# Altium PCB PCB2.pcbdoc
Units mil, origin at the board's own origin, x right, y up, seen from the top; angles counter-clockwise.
Board outline 4577.16 x 3555.26 mil, 4 copper layers (Top Layer, Inner1, Inner2, Bottom Layer); 87 components, 77 nets, 373 pads, 159 vias.
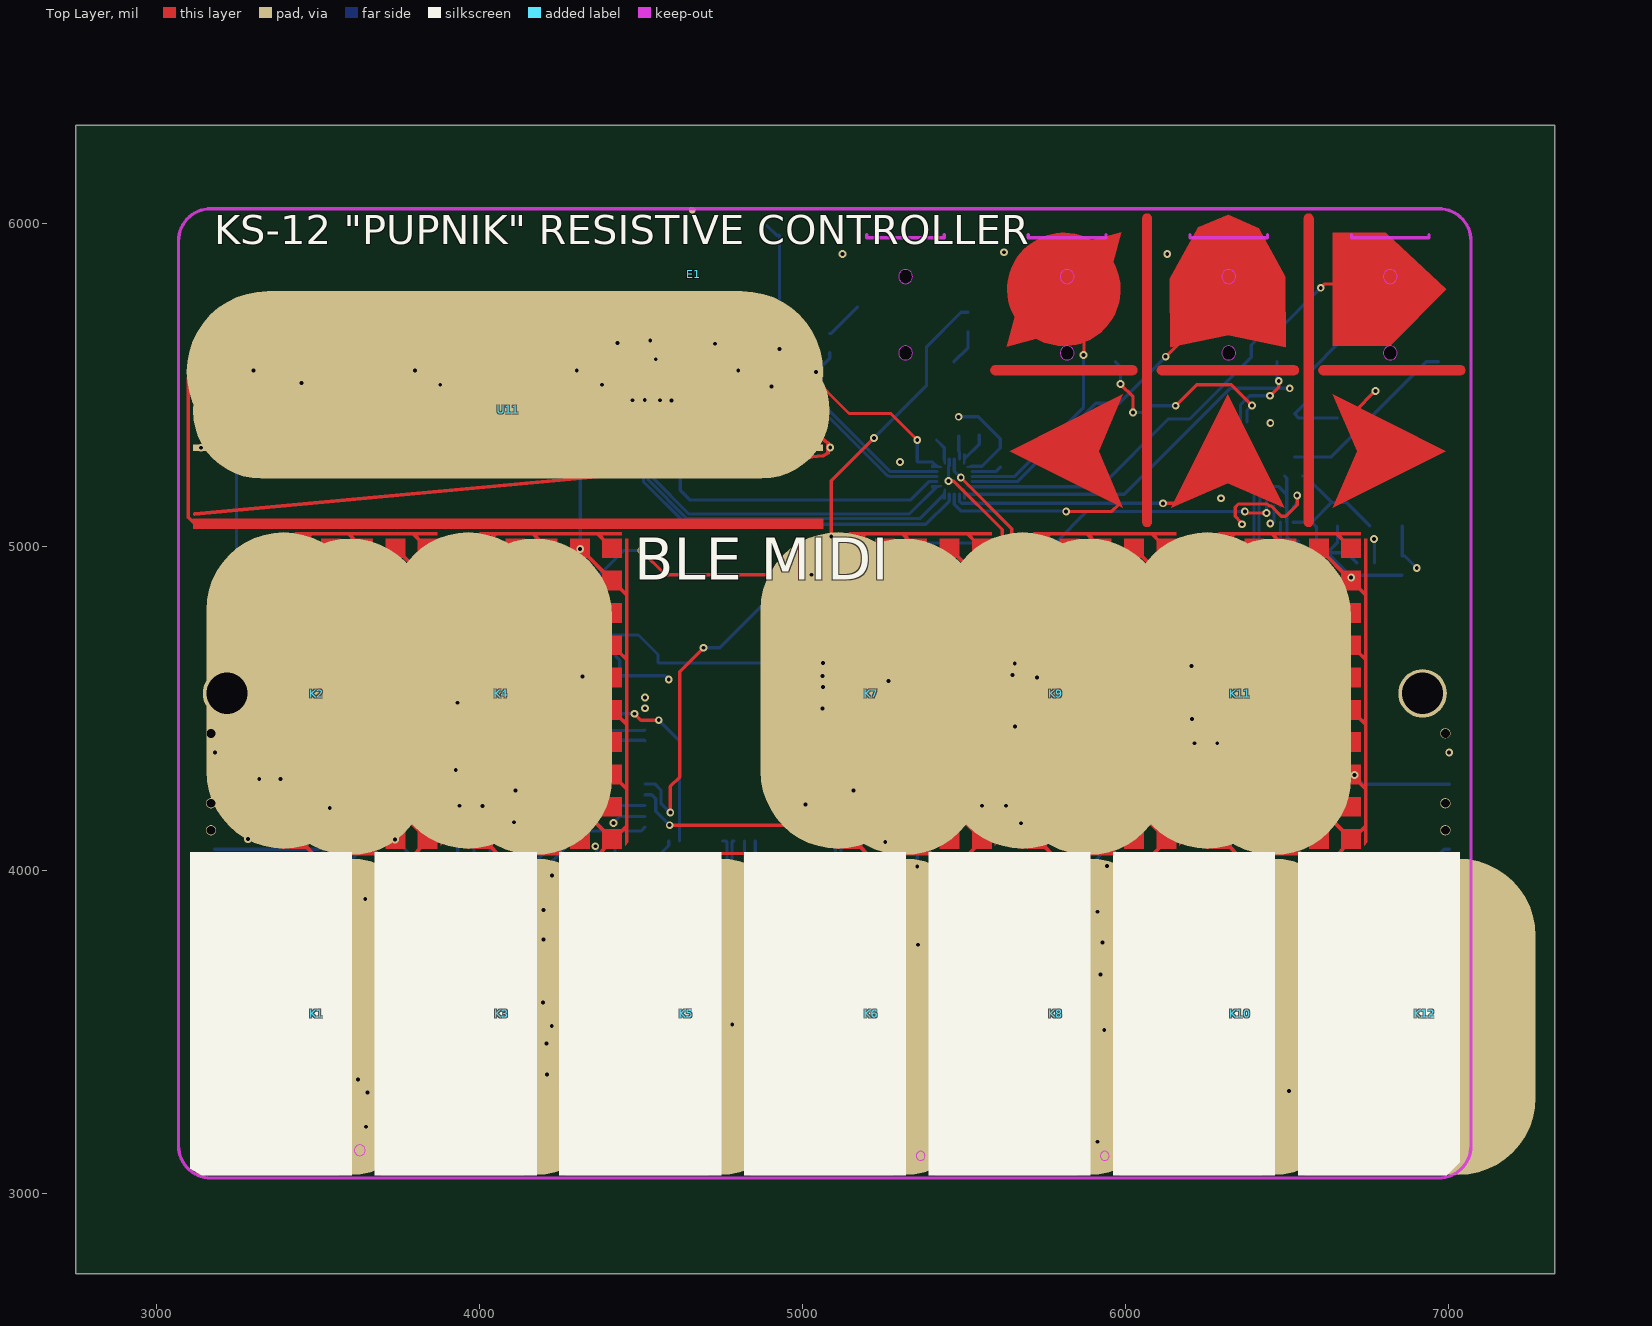
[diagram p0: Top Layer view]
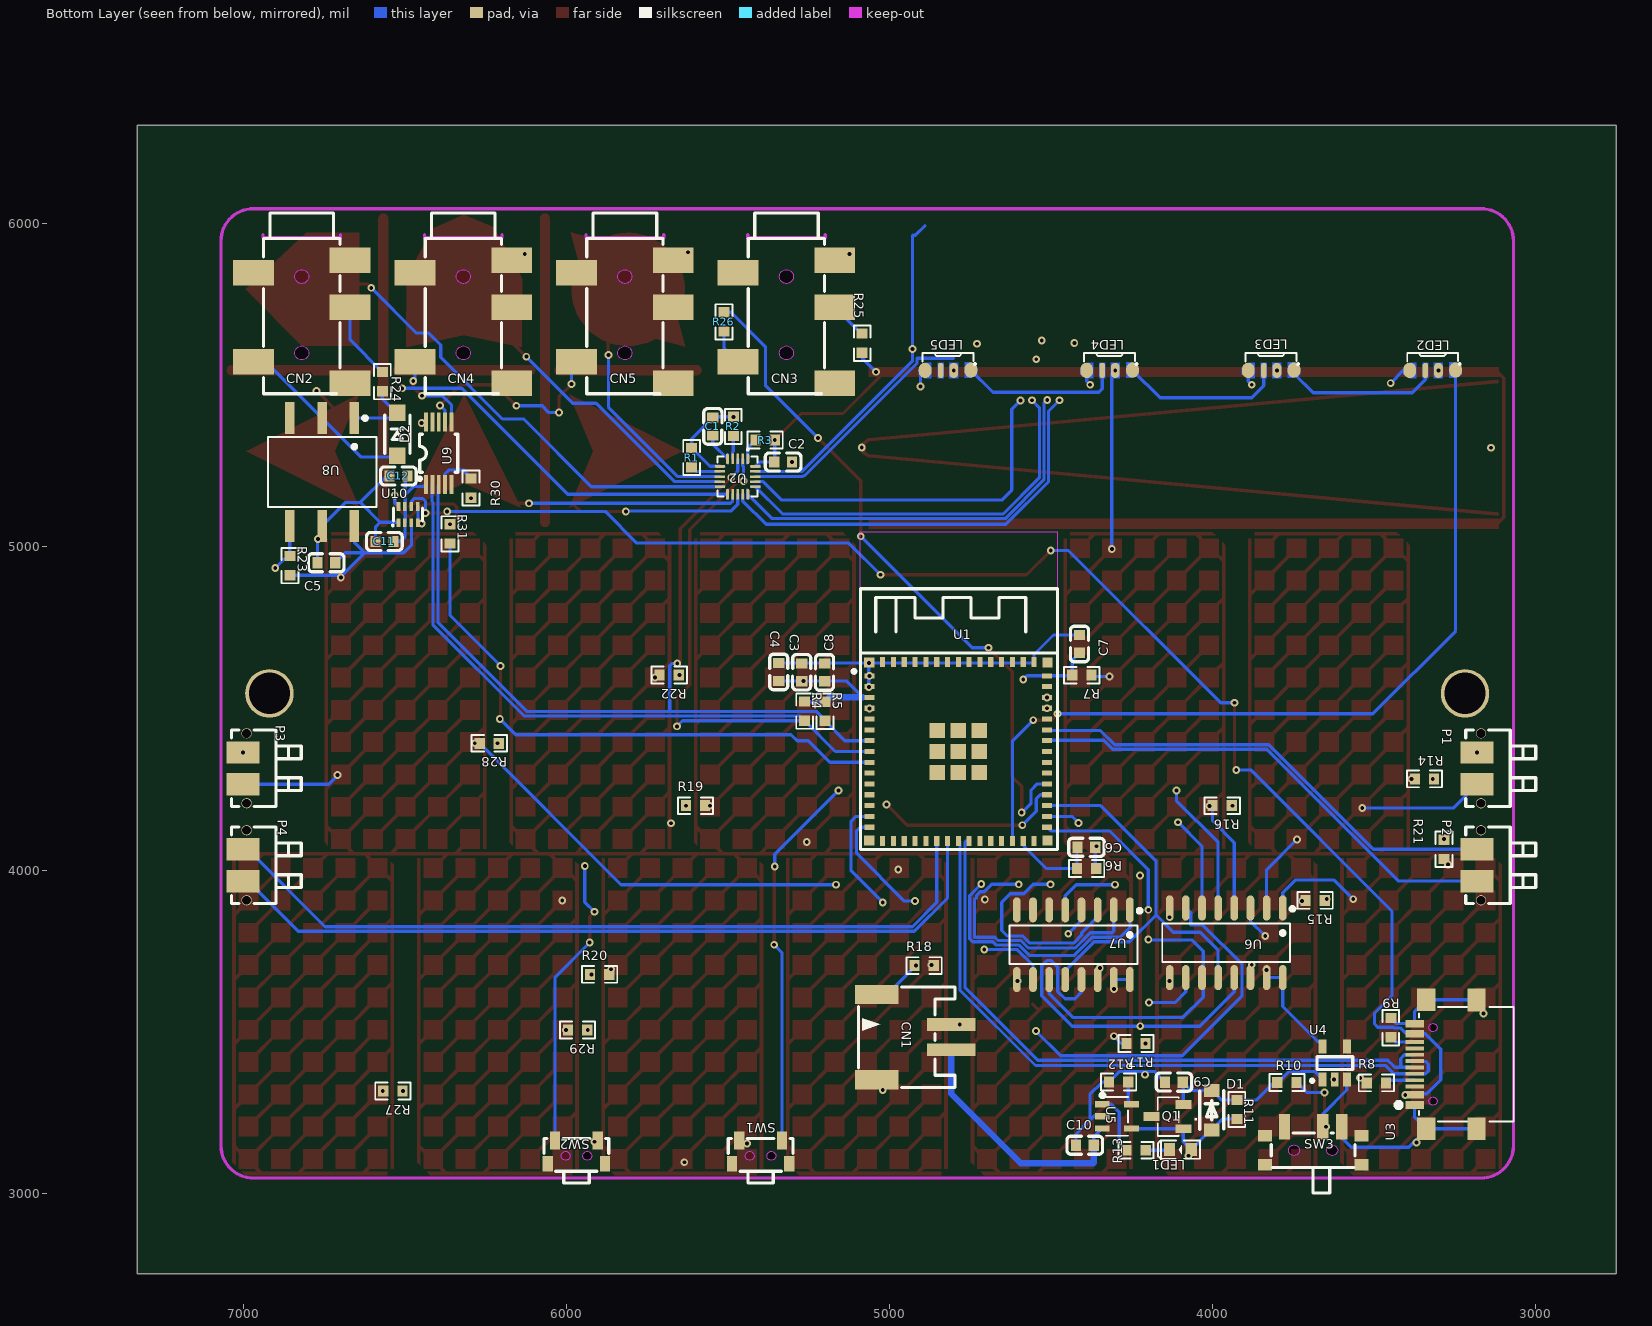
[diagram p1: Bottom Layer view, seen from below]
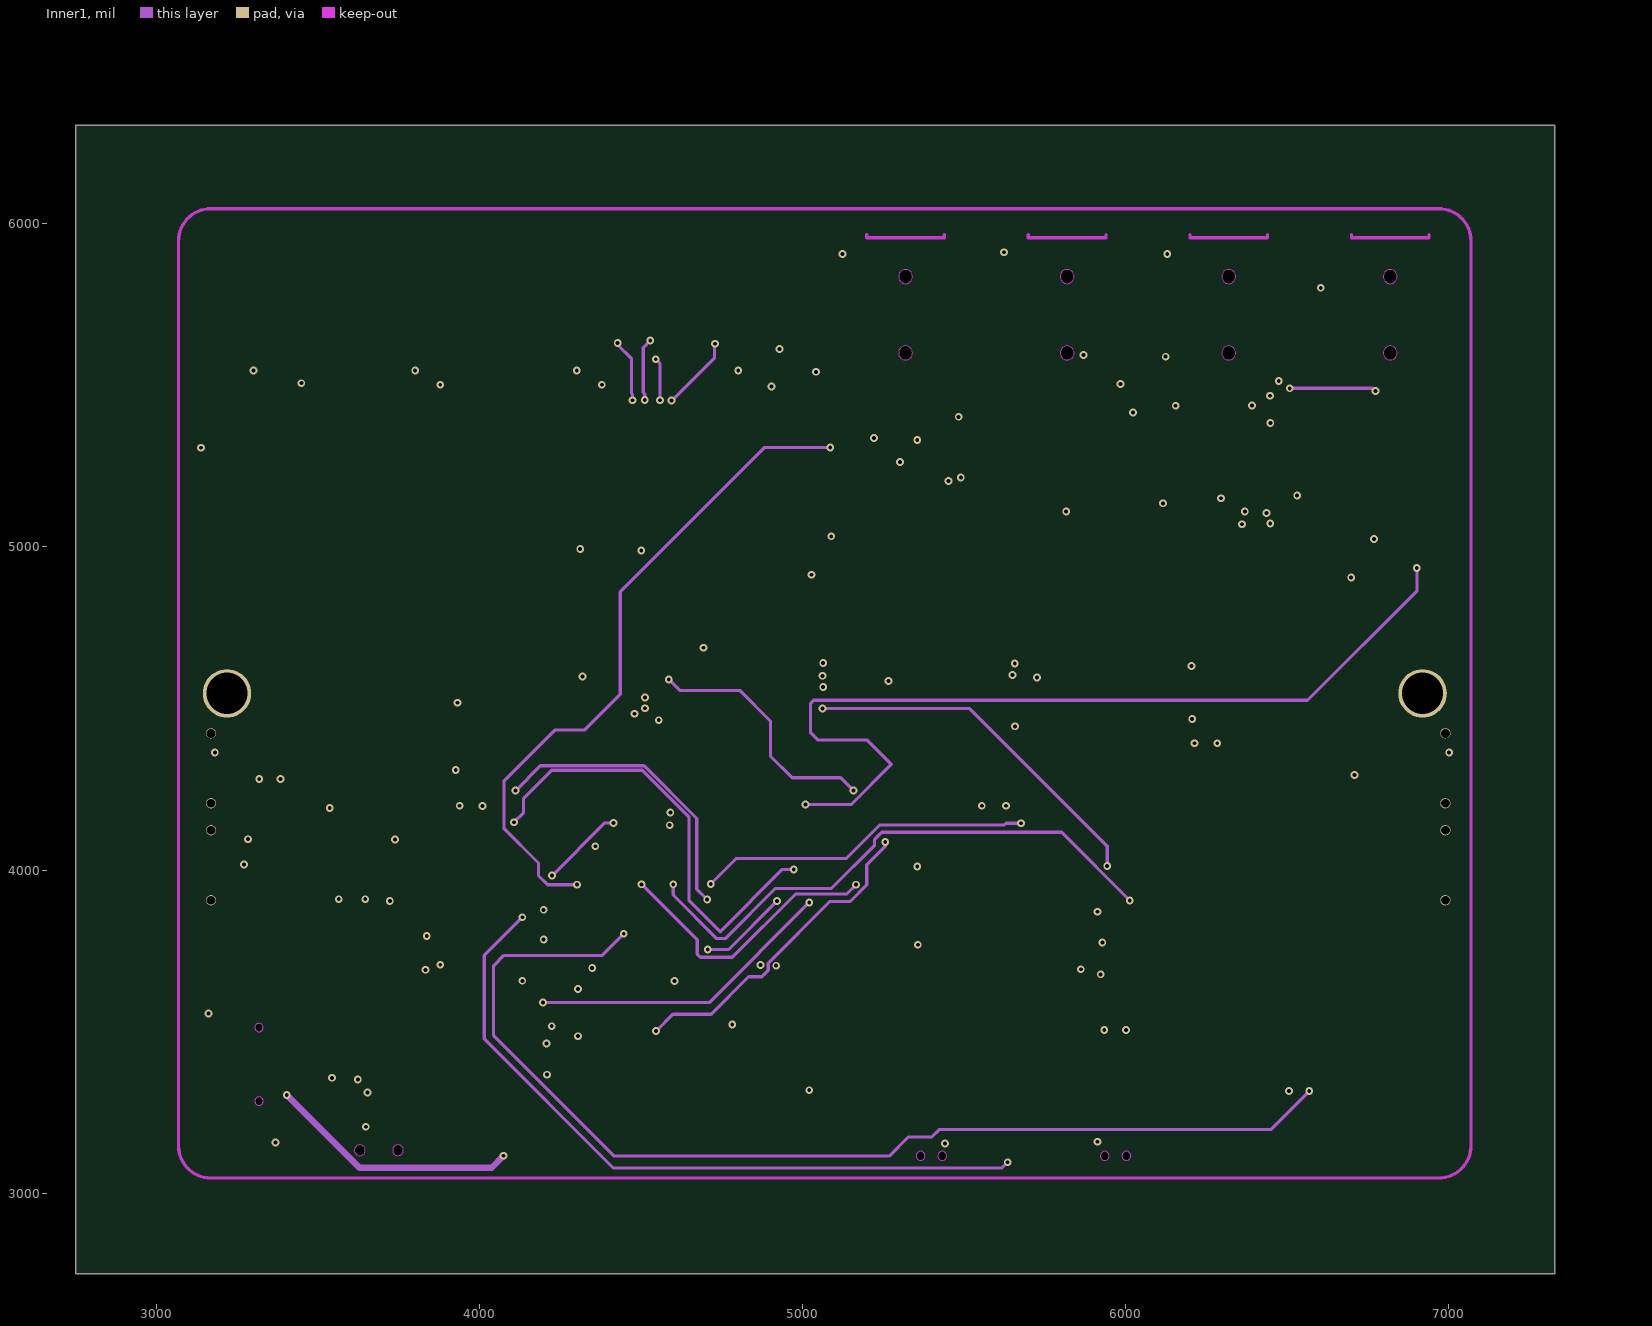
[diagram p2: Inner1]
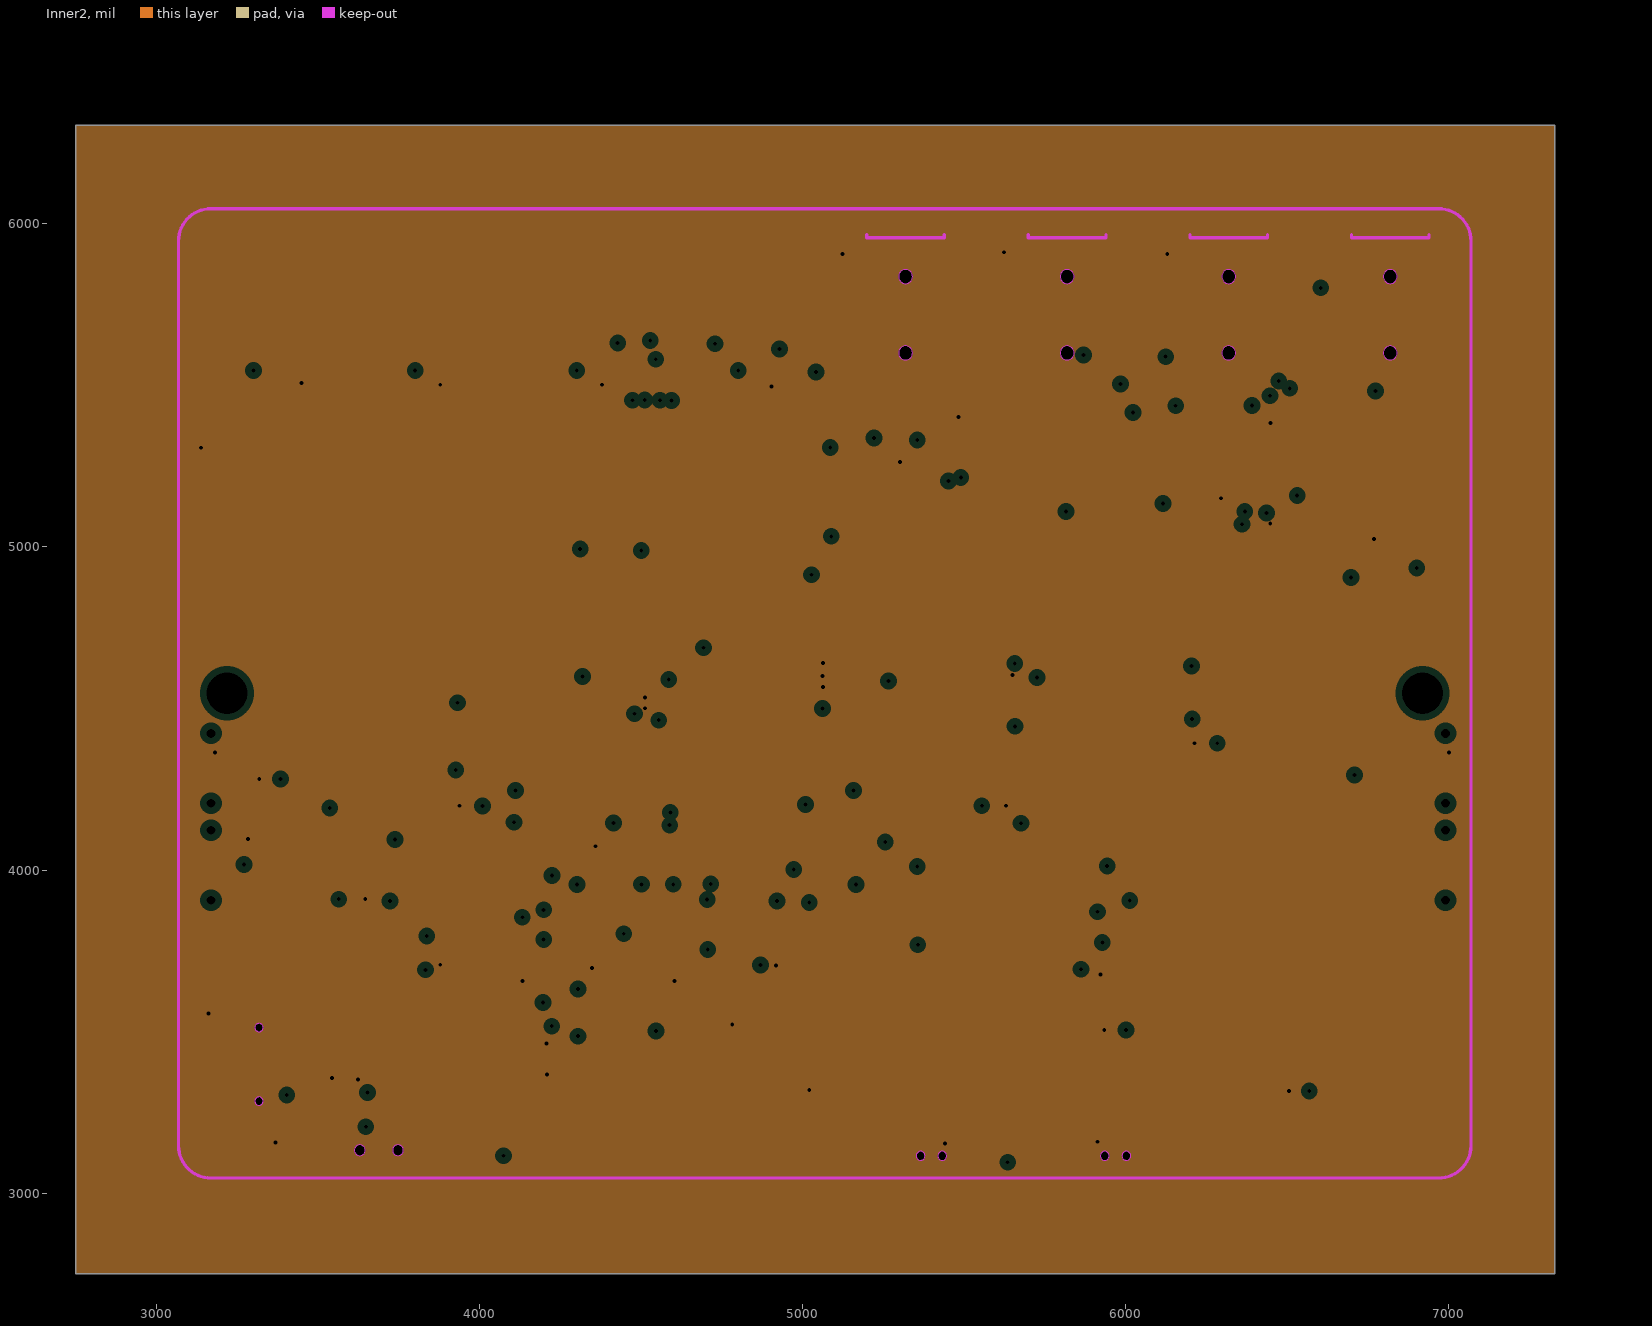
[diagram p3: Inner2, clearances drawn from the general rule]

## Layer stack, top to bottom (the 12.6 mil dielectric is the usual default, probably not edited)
Top Layer: signal copper (thickness not stored)
Dielectric: dielectric 12.6, FR-4, Dk 4.8
Inner1: signal copper (thickness not stored)
Dielectric: dielectric 12.6, FR-4, Dk 4.8
Inner2: plane copper (thickness not stored)
Dielectric: dielectric 12.6, FR-4, Dk 4.8
Bottom Layer: signal copper (thickness not stored)

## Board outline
7327.16,2750 2750,2750 2750,6305.26 7327.16,6305.26

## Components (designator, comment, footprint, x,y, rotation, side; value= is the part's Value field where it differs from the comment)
C1 "0.1u" C0603 5546.64,5372.74 r270 bottom
C2 "0.1u" C0603 5328.64,5262.74 r180 bottom
C3 "1u" C0603 5271.64,4611.74 r270 bottom
C4 "10u" C0603 5342.64,4612.74 r270 bottom
C5 "10u" C0603 6742.64,4950.74 r180 bottom
C6 "1u" C0603 4390.55,4070.38 r0 bottom
C7 "1u" C0603 4411.64,4699.74 r90 bottom
C8 "10u" C0603 5200.64,4611.74 r90 bottom
C9 "10u" C0603 4119.64,3343.74 r0 bottom
C10 "10u" C0603 4394.92,3148.1 r180 bottom
C11 "10u" C0603 6562.64,5016.74 r180 bottom
C12 "0.1u" C0603 6519.26,5219.49 r180 bottom
CN1 "BAT" CONN-SMD_P2.00_S2B-PH-SM4-TB-LF-SN 4923.64,3482.74 r270 bottom
CN2 "MIDI IN" AUDIO-SMD_PJ-327A5JJ 6818.64,5696.74 r180 bottom
CN3 "MIDI OUT" AUDIO-SMD_PJ-327A5JJ 5318.64,5696.74 r180 bottom
CN4 "CV" AUDIO-SMD_PJ-327A5JJ 6318.64,5696.74 r180 bottom
CN5 "GT" AUDIO-SMD_PJ-327A5JJ 5818.64,5696.74 r180 bottom
D1 "SM4007PL" SOD-123F_L2.8-W1.8-LS3.7-RD 4002.64,3256.74 r270 bottom
D2 "1N4148W" SOD-123FL_L2.6-W1.6-LS3.4-RD 6522.64,5348.74 r90 bottom
E1 "enc" enc 3218.64,6021.74 r0 top
K1 "key" key 3354.64,3555.74 r0 top
K2 "key" key 3639.64,4545.74 r180 top
K3 "key" key 3926.64,3555.74 r0 top
K4 "key" key 4210.64,4545.74 r180 top
K5 "key" key 4497.64,3555.74 r0 top
K6 "key" key 5069.64,3555.74 r0 top
K7 "key" key 5354.64,4545.74 r180 top
K8 "key" key 5640.64,3555.74 r0 top
K9 "key" key 5925.64,4545.74 r180 top
K10 "key" key 6211.64,3555.74 r0 top
K11 "key" key 6497.64,4545.74 r180 top
K12 "key" key 6783.64,3555.74 r0 top
LED1 "LED-0603_R" LED0603_RED 4099.64,3134.74 r0 bottom
LED2 "SK6812SIDE-A-RVS" LED-SMD_4P-L4.0-W1.6-L 3318.64,5546.74 r0 bottom
LED3 "SK6812SIDE-A-RVS" LED-SMD_4P-L4.0-W1.6-L 3818.64,5546.74 r0 bottom
LED4 "SK6812SIDE-A-RVS" LED-SMD_4P-L4.0-W1.6-L 4318.64,5546.74 r0 bottom
LED5 "SK6812SIDE-A-RVS" LED-SMD_4P-L4.0-W1.6-L 4818.64,5546.74 r0 bottom
P1 "PogoPIN 2PIN 2.54mm" "POGOPIN 2PIN 2.5MM" 3078.64,4196.74 r270 bottom
P2 "PogoPIN 2PIN 2.54mm" "POGOPIN 2PIN 2.5MM" 3078.64,3896.74 r270 bottom
P3 "PogoPIN 2PIN 2.54mm" "POGOPIN 2PIN 2.5MM" 6898.64,4196.74 r270 bottom
P4 "PogoPIN 2PIN 2.54mm" "POGOPIN 2PIN 2.5MM" 6898.64,3896.74 r270 bottom
Q1 "DMG3415U-7" SOT-23-3_L2.9-W1.6-P1.90-LS2.8-BR-CW 4139.64,3236.74 r180 bottom
R1 "75k" R0603 5611.98,5276.4 r270 bottom
R2 "10k" R0603 5483.07,5372.89 r270 bottom
R3 "10k" R0603 5384.64,5330.74 r0 bottom
R4 "10k" R0603 5262.37,4491.67 r270 bottom
R5 "10k" R0603 5199.37,4491.37 r270 bottom
R6 "1M" R0603 4389.64,4004.74 r0 bottom
R7 "5.1k" R0603 4404.46,4602.88 r0 bottom
R8 "5.1k" R0603 3492.89,3341.41 r180 bottom
R9 "5.1k" R0603 3448.23,3512.03 r270 bottom
R10 "100k" R0603 3769.64,3342.74 r180 bottom
R11 "100k" R0603 3924.64,3258.74 r270 bottom
R12 "5.1k" R0603 4290.64,3343.74 r0 bottom
R13 "5.1k" R0603 4236.64,3132.74 r0 bottom
R14 "100K" R0603 3343.99,4282.07 r0 bottom
R15 "100K" R0603 3682.48,3906.07 r0 bottom
R16 "100K" R0603 3970.14,4199.07 r0 bottom
R17 "100K" R0603 4236.89,3463.07 r0 bottom
R18 "100K" R0603 4892.59,3704.07 r180 bottom
R19 "100K" R0603 5600.04,4199.07 r180 bottom
R20 "100K" R0603 5896.79,3677.07 r180 bottom
R21 "100K" R0603 3283.3,4064.08 r270 bottom
R22 "100K" R0603 5681.49,4603.24 r0 bottom
R23 "470" R0603 6855.3,4942.08 r270 bottom
R24 "220" R0603 6569.19,5511.44 r270 bottom
R25 "33" R0603 5084.16,5630.41 r270 bottom
R26 "10" R0603 5512.16,5696.36 r90 bottom
R27 "100K" R0603 6536.64,3315.74 r0 bottom
R28 "100K" R0603 6238.48,4392.24 r0 bottom
R29 "100K" R0603 5964.99,3505.24 r0 bottom
R30 "5.1k" R0603 6294.97,5182.04 r90 bottom
R31 "10k" R0603 6359.6,5040.4 r270 bottom
SW1 "RST" SW-SMD_L4.7-W3.5-P3.35-EH 5398.64,3126.74 r0 bottom
SW2 "BOOT" SW-SMD_L4.7-W3.5-P3.35-EH 5968.64,3126.74 r0 bottom
SW3 "MK-12C02-G020" SW-SMD_MK-12C02-G020 3688.64,3146.74 r180 bottom
U1 "ESP32-S3-MINI-1-N8" BULETM-SMD_ESP32-S3-MINI-1-N8 4786.64,4366.74 r180 bottom
U2 "MPR121QR2" QFN-20_L3.0-W3.0-P0.40-BL 5469.64,5217.74 r0 bottom
U3 "GT-USB-9047A" USB-C-SMD_GT-USB-9047A 3278.64,3398.74 r90 bottom
U4 "AP2112K-3.3TRG1" SOT-25-5_L2.9-W1.6-P0.95-LS2.8-BL 3621.64,3402.74 r180 bottom
U5 "MCP73831T-2ACI/OT" SOT-23-5_L3.0-W1.7-P0.95-LS2.8-BL 4295.64,3237.74 r270 bottom
U6 "MCP3008-I/SL" SOIC-16_L9.9-W3.9-P1.27-LS6.0-BL 3957.64,3774.74 r0 bottom
U7 "MCP3008-I/SL" SOIC-16_L9.9-W3.9-P1.27-LS6.0-BL 4430.64,3768.74 r0 bottom
U8 "H11L1VSMT&amp;R" SMD-6_L8.6-W6.4-P2.54-LS9.4-BL 6755.64,5231.74 r0 bottom
U9 "MCP4728-E/UN" MSOP-10_L3.0-W3.0-P0.50-LS5.0-TL 6394.64,5289.74 r90 bottom
U10 "LM66200DRLR" SOT-583-8_L2.1-W1.2-P0.50-LS1.6-BL 6489.64,5099.74 r180 bottom
U11 "farts" farts 3093.64,5556.74 r0 top

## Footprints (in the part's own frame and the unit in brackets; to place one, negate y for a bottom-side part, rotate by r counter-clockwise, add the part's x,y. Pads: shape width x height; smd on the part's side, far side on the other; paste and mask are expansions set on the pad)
AUDIO-SMD_PJ-327A5JJ [mm]
  rect 3.2x2 smd: 1(3.8,4.85) 2(-3.8,3.85) 3(3.8,1.15) 4(-3.8,-3.15) 5(3.8,-4.85)
  Board Outline Layer lines w0.254: 3.048,6.604 -3.048,6.604 ; 3.048,6.604 -3.048,6.604 ; 3.048,6.604 3.048,6.858 3.048,6.604 ; -3.048,6.604 -3.048,6.858 -3.048,6.604
  Multi-Layer board cut-out: -0.55,3.55 -0.496,3.789 -0.343,3.98 -0.123,4.086 0.122,4.086 0.343,3.98 0.495,3.789 0.55,3.55 0.55,3.55 0.495,3.311 0.343,3.12 0.122,3.014 -0.123,3.014 -0.343,3.12 -0.496,3.311 -0.55,3.55
  Multi-Layer board cut-out: -0.55,-2.45 -0.496,-2.211 -0.343,-2.02 -0.123,-1.914 0.122,-1.914 0.343,-2.02 0.495,-2.211 0.55,-2.45 0.55,-2.45 0.495,-2.689 0.343,-2.88 0.122,-2.986 -0.123,-2.986 -0.343,-2.88 -0.496,-2.689 -0.55,-2.45
  Multi-Layer keep-out region: -0.55,3.55 -0.496,3.789 -0.343,3.98 -0.123,4.086 0.122,4.086 0.343,3.98 0.495,3.789 0.55,3.55 0.55,3.55 0.495,3.311 0.343,3.12 0.122,3.014 -0.123,3.014 -0.343,3.12 -0.496,3.311 -0.55,3.55
  Multi-Layer keep-out region: -0.55,-2.45 -0.496,-2.211 -0.343,-2.02 -0.123,-1.914 0.122,-1.914 0.343,-2.02 0.495,-2.211 0.55,-2.45 0.55,-2.45 0.495,-2.689 0.343,-2.88 0.122,-2.986 -0.123,-2.986 -0.343,-2.88 -0.496,-2.689 -0.55,-2.45
  silkscreen extent -3,-5.65 3,8.55
BULETM-SMD_ESP32-S3-MINI-1-N8 [mm]
  rect 0.8x0.4 smd: 1(-6.975,5.95) 2(-6.975,5.1) 3(-6.975,4.25) 4(-6.975,3.4) 5(-6.975,2.55) 6(-6.975,1.7) 7(-6.975,0.85) 8(-6.975,0) 9(-6.975,-0.85) 10(-6.975,-1.7) 11(-6.975,-2.55) 12(-6.975,-3.4) 13(-6.975,-4.25) 14(-6.975,-5.1) 15(-6.975,-5.95) 31(6.975,-5.95) 32(6.975,-5.1) 33(6.975,-4.25) 34(6.975,-3.4) 35(6.975,-2.55) 36(6.975,-1.7) 37(6.975,-0.85) 38(6.975,0) 39(6.975,0.85) 40(6.975,1.7) 41(6.975,2.55) 42(6.975,3.4) 43(6.975,4.25) 44(6.975,5.1) 45(6.975,5.95)
  rect 0.4x0.8 smd: 16(-5.95,-7.025) 17(-5.1,-7.025) 18(-4.25,-7.025) 19(-3.4,-7.025) 20(-2.55,-7.025) 21(-1.7,-7.025) 22(-0.85,-7.025) 23(0,-7.025) 24(0.85,-7.025) 25(1.7,-7.025) 26(2.55,-7.025) 27(3.4,-7.025) 28(4.25,-7.025) 29(5.1,-7.025) 30(5.95,-7.025) 46(5.95,7.025) 47(5.1,7.025) 48(4.25,7.025) 49(3.4,7.025) 50(2.55,7.025) 51(1.7,7.025) 52(0.85,7.025) 53(0,7.025) 54(-0.85,7.025) 55(-1.7,7.025) 56(-2.55,7.025) 57(-3.4,7.025) 58(-4.25,7.025) 59(-5.1,7.025) 60(-5.95,7.025)
  rect 0.8x0.8 smd: 61(7,7) 62(-7,-7) 63(7,-7) GND(-7,7)
  rect 1.2x1.2 smd: 64(-1.65,1.65) 65(0,1.65) 66(1.65,1.65) 67(-1.65,0) 68(0,0) 69(1.65,0) 70(-1.65,-1.65) 71(0,-1.65) 72(1.65,-1.65)
  silkscreen extent -8.34,-7.7 7.8,12.8
C0603 [mm]
  rect 0.8x0.9 smd: 1(-0.7,0) 2(0.7,0)
  silkscreen extent -1.41,-0.71 1.39,0.72
CONN-SMD_P2.00_S2B-PH-SM4-TB-LF-SN [mm]
  rect 1x3.8 smd: 1(-1,2.925) 2(1,2.925)
  rect 1.5x3.4 smd: 3(3.35,-2.925) 4(-3.35,-2.925)
  silkscreen extent -3.95,-4.37 3.95,3.22
enc [mil]
  round 20 smd: 1(1645,-370) 2(1440,20) 3(1245,-375)
farts [mil]
  oval 1970x500 smd: 1(985,-15)
  oval 1970x420 smd: 2(1005,-135.69)
  rect 1950x20 smd: 3(995,-250)
  Top Layer region: 1970,-470 1970,-500 20,-500 20,-487.07 1.46,-468.54 1.46,-468.54 0.38,-466.91 0,-465 0,-465 0,-35 0.38,-33.09 1.46,-31.46 1.46,-31.46 1.46,-31.46 20,-12.93 20,0 1970,0 1970,-30 20,-30 20,-27.07 10,-37.07 10,-462.93 20,-472.93 20,-470
  Top Layer region: 25.46,-459.98 25.23,-459.99 25,-460 25,-460 23.09,-459.62 21.46,-458.54 20.38,-456.91 20,-455 20,-455 20.6,-452.63 22.24,-450.83 24.54,-450.02 24.54,-450.02 1968.42,-270.13 1980,-263.25 1980,-237.68 1968.28,-229.86 24.54,-49.98 24.54,-49.98 22.24,-49.17 20.6,-47.37 20,-45 20,-45 20.38,-43.09 21.46,-41.46 23.09,-40.38 25,-40 25,-40 25.23,-40.01 25.46,-40.02 25.46,-40.02 1970.46,-220.02 1970.46,-220.02 1971.67,-220.29 1972.77,-220.84 1972.77,-220.84 1972.77,-220.84 1987.77,-230.84 1987.77,-230.84 1989.41,-232.64 1990,-235 1990,-235 1990,-266.1 1989.34,-268.57 1987.55,-270.4 1987.55,-270.4 1987.55,-270.4 1972.55,-279.3 1971.54,-279.76 1970.46,-279.98 1970.46,-279.98 1970.46,-279.98
key [mil]
  oval 480x980 smd: 1(40,10) 2(245,-10)
  Top Layer region: 191 vertices and 0 holes, not listed, extent -250,-480 230,500
  Top Layer region: 189 vertices and 0 holes, not listed, extent -230,-500 250,480
LED0603_RED [mm]
  rect 0.9x1 smd: 1(-0.85,0) 2(0.85,0)
  silkscreen extent -1.54,-0.73 1.75,0.73
LED-SMD_4P-L4.0-W1.6-L [mm]
  oval 1x1.2 smd: 1(-1.8,-0.012) 4(1.8,0.013)
  oval 0.7x1.2 smd: 2(-0.45,0.013)
  oval 0.45x1.2 smd: 3(0.575,0.013)
  Top Layer region: 1.3,0.612 1.3,-0.588 1.85,-0.587 1.85,-0.188 2.3,-0.188 2.3,0.362 1.85,0.362 1.85,0.612
  Top Layer region: 0.35,-0.588 0.8,-0.588 0.8,0.612 0.35,0.612
  Top Layer region: -0.8,0.613 -0.8,-0.587 -0.1,-0.587 -0.1,0.613
  Top Layer region: -1.3,0.588 -1.3,-0.612 -1.85,-0.612 -1.85,-0.212 -2.3,-0.212 -2.3,0.338 -1.85,0.338 -1.85,0.588
  silkscreen extent -2.2,-1.36 2,-0.41
MSOP-10_L3.0-W3.0-P0.50-LS5.0-TL [mil]
  rect 59.05x12 smd: 1(-96.5,39.37) 2(-96.5,19.68) 3(-96.5,0) 4(-96.5,-19.69) 5(-96.5,-39.37) 6(96.5,-39.37) 7(96.5,-19.69) 8(96.5,0) 9(96.5,19.68) 10(96.5,39.37)
  silkscreen extent -84,-59 59,64
"POGOPIN 2PIN 2.5MM" [mm]
  rect 1.75x2.6 smd: 1(-4.25,-2.6) 2(-1.75,-2.6)
  round 0.8 hole 0.7: 3(-5.75,-2.3) 4(-0.25,-2.3)
  silkscreen extent -6,-3.5 0,2
QFN-20_L3.0-W3.0-P0.40-BL [mm]
  oval 0.224x0.825 smd: 1(-0.8,-1.388) 5(0.8,-1.388) 11(0.8,1.388) 15(-0.8,1.388)
  rect 0.2x0.825 smd: 2(-0.4,-1.388) 3(0,-1.388) 4(0.4,-1.388) 12(0.4,1.388) 13(0,1.388) 14(-0.4,1.388)
  oval 0.825x0.224 smd: 6(1.388,-0.8) 10(1.388,0.8) 16(-1.387,0.8) 20(-1.388,-0.8)
  rect 0.825x0.2 smd: 7(1.388,-0.4) 8(1.388,0) 9(1.388,0.4) 17(-1.387,0.4) 18(-1.387,0) 19(-1.387,-0.4)
  Top Layer region: 0.688,-1.8 0.688,-0.975 0.8,-0.975 0.912,-1.388 0.912,-1.8
  Top Layer region: -1.8,-0.688 -0.975,-0.688 -0.975,-0.8 -1.388,-0.912 -1.8,-0.912
  Top Layer region: -0.688,1.8 -0.688,0.975 -0.8,0.975 -0.912,1.388 -0.912,1.8
  Top Layer region: 1.8,0.688 0.975,0.688 0.975,0.8 1.388,0.912 1.8,0.912
  Top Layer region: 1.8,-0.688 0.975,-0.688 0.975,-0.8 1.388,-0.912 1.8,-0.912
  Top Layer region: 0.688,1.8 0.688,0.975 0.8,0.975 0.912,1.388 0.912,1.8
  Top Layer region: -1.8,0.688 -0.975,0.688 -0.975,0.8 -1.387,0.912 -1.8,0.912
  Top Layer region: -0.688,-1.8 -0.688,-0.975 -0.8,-0.975 -0.912,-1.388 -0.912,-1.8
  silkscreen extent -1.58,-2.17 1.58,1.58
R0603 [mil]
  rect 31.75x34.02 smd: 1(-29.66,0) 2(29.66,0)
  silkscreen extent -55,-26 55,26
SMD-6_L8.6-W6.4-P2.54-LS9.4-BL [mil]
  rect 29.76x99.37 smd: 1(-100,-166.81) 2(0,-166.81) 3(100,-166.81) 4(100,166.81) 5(0,166.81) 6(-100,166.81)
  silkscreen extent -168,-173 168,108
SOD-123F_L2.8-W1.8-LS3.7-RD [mm]
  rect 1x1.2 smd: 1(-1.55,0) 2(1.55,0)
  silkscreen extent -1.52,-0.93 1.49,0.95
SOD-123FL_L2.6-W1.6-LS3.4-RD [mm]
  rect 1.3x1.3 smd: 1(1.7,0) 2(-1.7,0)
  silkscreen extent -1.5,-1 1.5,1
SOIC-16_L9.9-W3.9-P1.27-LS6.0-BL [mil]
  oval 23.7x77.6 smd: 1(-175,-107.7) 2(-125,-107.7) 3(-75,-107.7) 4(-25,-107.7) 5(25,-107.7) 6(75,-107.7) 7(125,-107.7) 8(175,-107.7) 9(175,107.7) 10(125,107.7) 11(75,107.7) 12(25,107.7) 13(-25,107.7) 14(-75,107.7) 15(-125,107.7) 16(-175,107.7)
  silkscreen extent -211,-111 198,60
SOT-23-3_L2.9-W1.6-P1.90-LS2.8-BR-CW [mm]
  rect 1.25x0.7 smd: 1(1.25,-0.95) 2(-1.25,0) 3(1.25,0.95)
  silkscreen extent -0.76,-1.52 2.28,1.52
SOT-23-5_L3.0-W1.7-P0.95-LS2.8-BL [mm]
  rect 0.49x1.157 smd: 1(-0.95,-1.154) 2(0,-1.154) 3(0.95,-1.154)
  rect 0.49x1.175 smd: 4(0.95,1.154) 5(-0.95,1.154)
  silkscreen extent -1.8,-1.29 1.53,0.85
SOT-25-5_L2.9-W1.6-P0.95-LS2.8-BL [mil]
  rect 24.5x43.5 smd: 1(-37.39,-51.18) 2(-0.03,-51.18) 3(37.39,-51.18) 4(37.39,51.18) 5(-37.39,51.18)
  silkscreen extent -75,-60 56,20
SOT-583-8_L2.1-W1.2-P0.50-LS1.6-BL [mm]
  rect 0.28x0.68 smd: 1(-0.75,-0.64) 2(-0.25,-0.64) 3(0.25,-0.64) 4(0.75,-0.64) 5(0.75,0.64) 6(0.25,0.64) 7(-0.25,0.64) 8(-0.75,0.64)
  silkscreen extent -1.27,-0.93 1.14,0.51
SW-SMD_L4.7-W3.5-P3.35-EH [mm]
  rect 0.8x1.4 smd: 1(-1.675,-0.917) 2(1.675,-0.917)
  rect 0.8x1.2 smd: 3(-2.25,0.917) 4(2.25,0.917)
  Multi-Layer board cut-out: -0.5,0.282 -0.535,0.131 -0.632,0.009 -0.772,-0.059 -0.928,-0.059 -1.068,0.009 -1.165,0.131 -1.2,0.282 -1.2,0.282 -1.165,0.434 -1.068,0.556 -0.928,0.624 -0.772,0.624 -0.632,0.556 -0.535,0.434 -0.5,0.282
  Multi-Layer board cut-out: 1.2,0.282 1.165,0.131 1.068,0.009 0.928,-0.059 0.772,-0.059 0.632,0.009 0.535,0.131 0.5,0.282 0.5,0.282 0.535,0.434 0.632,0.556 0.772,0.624 0.928,0.624 1.068,0.556 1.165,0.434 1.2,0.282
  Multi-Layer keep-out region: -0.5,0.282 -0.535,0.131 -0.632,0.009 -0.772,-0.059 -0.928,-0.059 -1.068,0.009 -1.165,0.131 -1.2,0.282 -1.2,0.282 -1.165,0.434 -1.068,0.556 -0.928,0.624 -0.772,0.624 -0.632,0.556 -0.535,0.434 -0.5,0.282
  Multi-Layer keep-out region: 1.2,0.282 1.165,0.131 1.068,0.009 0.928,-0.059 0.772,-0.059 0.632,0.009 0.535,0.131 0.5,0.282 0.5,0.282 0.535,0.434 0.632,0.556 0.772,0.624 0.928,0.624 1.068,0.556 1.165,0.434 1.2,0.282
  silkscreen extent -2.54,-1.07 2.54,2.43
SW-SMD_MK-12C02-G020 [mm]
  rect 0.9x2 smd: 1(-2.25,1.491) 2(0.75,1.491) 3(2.25,1.491)
  rect 1.1x0.93 smd: 4(3.8,0.779) 5(3.8,-1.491) 6(-3.8,-1.491) 7(-3.8,0.779)
  Multi-Layer board cut-out: 1.075,-0.356 1.117,-0.171 1.235,-0.023 1.405,0.059 1.595,0.059 1.765,-0.023 1.883,-0.171 1.925,-0.356 1.925,-0.356 1.883,-0.54 1.765,-0.688 1.595,-0.77 1.405,-0.77 1.235,-0.688 1.117,-0.54 1.075,-0.356
  Multi-Layer board cut-out: -1.925,-0.356 -1.883,-0.171 -1.765,-0.023 -1.595,0.059 -1.405,0.059 -1.235,-0.023 -1.117,-0.171 -1.075,-0.356 -1.075,-0.356 -1.117,-0.54 -1.235,-0.688 -1.405,-0.77 -1.595,-0.77 -1.765,-0.688 -1.883,-0.54 -1.925,-0.356
  Multi-Layer keep-out region: 1.075,-0.356 1.117,-0.171 1.235,-0.023 1.405,0.059 1.595,0.059 1.765,-0.023 1.883,-0.171 1.925,-0.356 1.925,-0.356 1.883,-0.54 1.765,-0.688 1.595,-0.77 1.405,-0.77 1.235,-0.688 1.117,-0.54 1.075,-0.356
  Multi-Layer keep-out region: -1.925,-0.356 -1.883,-0.171 -1.765,-0.023 -1.595,0.059 -1.405,0.059 -1.235,-0.023 -1.117,-0.171 -1.075,-0.356 -1.075,-0.356 -1.117,-0.54 -1.235,-0.688 -1.405,-0.77 -1.595,-0.77 -1.765,-0.688 -1.883,-0.54 -1.925,-0.356
  silkscreen extent -3.3,-3.71 3.3,0.99
USB-C-SMD_GT-USB-9047A [mm]
  rect 1.8x1.45 smd: 12(-5.07,1.524) 13(5.07,1.524)
  rect 1.8x1.4 smd: 14(-5.07,-2.436) 15(5.07,-2.436)
  rect 0.6x1.45 smd: A1B12(-3.2,2.437) A4B9(-2.4,2.437) A9B4(2.4,2.437) A12B1(3.2,2.437)
  rect 0.3x1.45 smd: A5(-1.25,2.437) A6(-0.25,2.437) A7(0.25,2.437) A8(1.25,2.437) B5(1.75,2.437) B6(0.75,2.437) B7(-0.75,2.437) B8(-1.75,2.437)
  Multi-Layer board cut-out: 2.89,1.319 3.031,1.286 3.144,1.196 3.207,1.066 3.207,0.921 3.144,0.791 3.031,0.701 2.89,0.669 2.89,0.669 2.749,0.701 2.636,0.791 2.573,0.921 2.573,1.066 2.636,1.196 2.749,1.286 2.89,1.319
  Multi-Layer board cut-out: -2.89,1.318 -2.749,1.286 -2.636,1.196 -2.573,1.065 -2.573,0.921 -2.636,0.791 -2.749,0.7 -2.89,0.668 -2.89,0.668 -3.031,0.7 -3.144,0.791 -3.207,0.921 -3.207,1.065 -3.144,1.196 -3.031,1.286 -2.89,1.318
  Multi-Layer keep-out region: 2.89,1.319 3.031,1.286 3.144,1.196 3.207,1.066 3.207,0.921 3.144,0.791 3.031,0.701 2.89,0.669 2.89,0.669 2.749,0.701 2.636,0.791 2.573,0.921 2.573,1.066 2.636,1.196 2.749,1.286 2.89,1.319
  Multi-Layer keep-out region: -2.89,1.318 -2.749,1.286 -2.636,1.196 -2.573,1.065 -2.573,0.921 -2.636,0.791 -2.749,0.7 -2.89,0.668 -2.89,0.668 -3.031,0.7 -3.144,0.791 -3.207,0.921 -3.207,1.065 -3.144,1.196 -3.031,1.286 -2.89,1.318
  silkscreen extent -4.5,-5.36 4.5,3.89

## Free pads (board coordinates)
  round 150 hole 128: 73(3218.64,4546.74) 73(6918.64,4546.74)

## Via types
v1: diameter 24.02, hole 12.01, Top Layer to Bottom Layer, 159 vias

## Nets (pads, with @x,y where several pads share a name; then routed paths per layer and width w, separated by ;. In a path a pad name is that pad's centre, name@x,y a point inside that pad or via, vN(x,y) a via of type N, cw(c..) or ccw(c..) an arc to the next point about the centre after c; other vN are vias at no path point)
3V3: C2.1 C3.2 C4.2 C5.2 C8.1 K1.1 K2.1 K3.1 K4.1 K5.1 K6.1 K7.1 K8.1 K9.1 K10.1 K11.1 K12.1 LED2.2 LED3.2 LED4.2 LED5.2 P1.2 P3.2 R3.1 R4.1 R5.1 R7.1 R23.2 R25.2 U1.3 U2.20 U4.5 U6.15 U6.16 U7.15 U7.16 U8.6 U10.3 U11.1 | length 4573
  Top Layer w10: U11.1 5014.64,5541.74 5143.64,5412.74 5272.98,5412.74 v1(5354.98,5330.74) ; K5.1 K5.1@4556.66,3584.76 ; 4728.64,4050.74 4853.64,4050.74 4855.64,4052.74
  Bottom Layer w10: P1.2 3254.9,4191.74 v1(3536.64,4191.74) ; U4.5 3782.64,3577.53 U6.16 U6.15 ; U7.16 U7.15 ; v1(4300.93,5546.24) 4311.64,5535.53 v1(4311.64,4993.74) ; v1(4318.64,4598.74) 4370.66,4598.74 R7.1 ; v1(5041.64,5541.74) 5084.16,5584.26 R25.2 ; U1.3 5082,4534.07 5133.11,4585.18 v1(5265.86,4585.18) C4.2 ; R5.1 5262.07,4521.03 R4.1 ; v1(5354.98,5330.74) 5354.98,5263.96 C2.1 5401.51,5262.74 U2.20 ; U10.3@6478.8,5076.54 6478.8,5006.58 6503.64,4981.74 6623.64,4981.74 ; U8.6 6655.64,5013.74 6623.64,4981.74 ; v1(6707.64,4293.74) 6735.74,4265.64 P3.2 ; C5.2 6684.08,4981.74 6623.64,4981.74 ; R23.2 6692.96,4912.42 6623.64,4981.74
  Bottom Layer w20: 5082,4534.07 5186.33,4534.07 R5.1
  other v1: 4304.64,3631.74 3832.64,3691.08 6697.64,4905.47 3300.93,5546.24 3800.93,5546.24 4800.93,5546.24
$1N143: R1.2 U2.7 | length 93.2
  Bottom Layer w10: U2.7 5598.73,5233.49 R1.2
$1N157: R2.2 U2.4 | length 71.8
  Bottom Layer w10: R2.2 5483.07,5295.94 5485.4,5293.61 U2.4
$1N175: R3.2 U2.1 | length 68.2
  Bottom Layer w10: R3.2 5438.15,5306.89 U2.1
$1N193: C1.2 U2.5 | length 91.7
  Bottom Layer w10: U2.5 5546.64,5317.86 C1.2
$1N354: C6.2 R6.2 U1.29 | length 276.4
  Bottom Layer w10: C6.2 4419.3,4069.18 R6.2 4514.64,4004.74 4585.85,4075.95 U1.29
$1N512: C9.1 D1.1 Q1.3 R10.1 R11.1 U4.1 | length 588.9
  Bottom Layer w10: U4.1 3684.21,3376.74 3762.14,3376.74 3796.14,3342.74 3796.14,3355.41 3863.15,3288.4 R11.1 3973.28,3288.4 D1.1 4066.1,3317.76 C9.1@4090.44,3342.1 ; Q1.3 C9.1@4090.44,3342.1 ; C9.1 C9.1@4090.44,3342.1
$1N704: C10.2 CN1.2 U5.3 | length 783.6
  Bottom Layer w10: U5.3 4367.36,3174.04 C10.2
  Bottom Layer w20: C10.2 4367.36,3094.02 4368.64,3092.74 4593.64,3092.74 4808.48,3307.58 CN1.2
$1N1108: LED2.3 LED3.1 | length 487.9
  Bottom Layer w10: LED2.3 3341.28,5517.62 3382.16,5476.74 3688.64,5476.74 3747.78,5535.88 LED3.1
$1N1109: LED3.3 LED4.1 | length 504.5
  Bottom Layer w10: LED3.3 3841.28,5499.1 3878.64,5461.74 4162.29,5461.74 LED4.1
$1N1133: LED4.3 LED5.1 | length 496.3
  Bottom Layer w10: LED4.3 4341.28,5489.1 4351.65,5478.73 4679.28,5478.73 LED5.1
$1N1275: CN2.4 D2.2 U8.2 | length 567.8
  Bottom Layer w10: D2.2@6522.64,5277.81 6634.9,5277.81 U8.2 6929.81,5572.72 CN2.4
$1N1289: CN2.3 R24.1 | length 242.3
  Bottom Layer w10: R24.1 6669.04,5640.96 CN2.3
$1N1451: C11.2 C12.2 U9.1 U10.2 U10.7 | length 303.7
  Bottom Layer w10: U9.1@6438.01,5190.24 6441.51,5186.74 6473.64,5186.74 6498.48,5161.9 ; C12.2 6498.48,5212.71 6498.48,5161.9 ; U10.2@6498.48,5076.54 6498.48,5126.94 6498.48,5161.9 ; U10.2 6499.48,5029.9 6511.64,5017.74 6534.08,5017.74 C11.2
$1N1517: CN4.4 U9.6 | length 274.7
  Top Layer w10: v1(6446.64,5467.74) 6473.64,5494.74 v1(6473.64,5513.74)
  Bottom Layer w10: U9.6 6355.27,5439.37 6383.64,5467.74 v1(6446.64,5467.74) ; CN4.4 6468.24,5519.14 v1(6473.64,5513.74)
$1N1518: CN5.4 U9.7 | length 667.6
  Top Layer w10: v1(5983.64,5503.74) 6022.64,5464.74 v1(6022.64,5415.74) ; v1(6154.64,5436.74) 6219.64,5501.74 6326.64,5501.74 v1(6390.64,5437.74)
  Bottom Layer w10: CN5.4 5983.64,5557.32 v1(5983.64,5503.74) ; v1(6022.64,5415.74) 6053.64,5415.74 6074.64,5436.74 v1(6154.64,5436.74) ; U9.7 6374.95,5422.05 v1(6390.64,5437.74)
$1N1636: R8.2 U3.A5 | length 92
  Bottom Layer w10: U3.A5 3455.11,3349.53 R8.2
$1N1637: R9.2 U3.B5 | length 79.8
  Bottom Layer w10: U3.B5 3433.5,3467.64 R9.2
$1N1651: R13.2 U5.1 | length 189.6
  Bottom Layer w10: R13.2 4288.64,3155.08 4288.64,3250.5 4313.29,3275.14 U5.1
$1N1656: R12.1 U5.5 | length 73.1
  Bottom Layer w10: U5.5 4260.98,3285.9 R12.1
$1N1659: LED1.2 R13.1 | length 74.7
  Bottom Layer w10: LED1.2 4135.1,3132.74 R13.1
$1N1720: D2.1 R24.2 U8.1 | length 227.8
  Bottom Layer w10: R24.2 6569.19,5458.21 6522.64,5411.67 6535.76,5398.55 U8.1
$1N1727: CN3.4 R26.1 | length 112.2
  Bottom Layer w10: CN3.4 5512.16,5616.64 R26.1
$1N1728: CN3.3 R25.1 | length 118.8
  Bottom Layer w10: R25.1 5087.1,5660.07 CN3.3
$1N1745: R30.2 U9.4 | length 131.6
  Bottom Layer w10: R30.2@6292.97,5211.7 6317.01,5235.74 ; 6317.01,5237.74 6363.64,5237.74 6376.95,5224.43 U9.4@6376.95,5192.24
$1N1760: R31.1 U10.8 | length 346.8
  Top Layer w10: v1@6356.64,5076.74 6338.64,5094.74 6338.64,5122.74 6348.64,5132.74 6437.64,5132.74 6443.64,5126.74 6449.64,5126.74 6481.64,5094.74 6494.64,5094.74 6530.64,5130.74 v1(6530.64,5158.74)
  Bottom Layer w10: U10.8 6530.64,5136.41 v1(6530.64,5158.74)
  other v1: 6359.6,5070.06
$1N7028: U2.19 | length 1068
  Bottom Layer w10: 4889.64,5994.74 4919.64,5964.74 4926.64,5964.74 4928.64,5962.74 v1(4928.64,5612.74) 4928.64,5574.74 5269.89,5233.49 U2.19
$1N7037: U2.18 | length 773.7
  Bottom Layer w10: 4801.64,5583.74 4914.63,5583.74 4914.63,5568.93 5264.09,5219.47 5268.87,5219.51 5270.64,5217.74 U2.18
$1N7042: U2.17 | length 1344.2
  Inner1 w10: v1(4594.64,5452.74) 4727.64,5585.74 v1@4727.64,5623.74
  Bottom Layer w10: v1(4594.64,5452.74) 4621.64,5425.74 4621.64,5175.74 4652.64,5144.74 5333.64,5144.74 5390.89,5201.99 U2.17
  other v1: 4728.89,5628.86
$1N7048: E1.3 U2.16 | length 1342.9
  Inner1 w10: v1(4545.64,5580.74) 4558.64,5567.74 v1(4558.64,5453.74)
  Bottom Layer w10: v1(4558.64,5453.74) 4535.67,5430.77 4535.67,5213.35 4647.27,5101.76 5330.54,5101.76 U2.16
$1N7054: E1.2 U2.15 | length 1443.9
  Inner1 w10: v1(4511.64,5454.74) 4511.64,5472.74 4506.64,5477.74 4506.64,5616.74 v1(4528.64,5638.74)
  Bottom Layer w10: v1(4511.64,5454.74) 4521.66,5444.72 4521.66,5207.55 4641.46,5087.74 5362.78,5087.74 U2.15
$1N7061: E1.1 U2.14 | length 1508.2
  Inner1 w10: v1@4427.64,5624.74 4470.64,5581.74 4470.64,5475.74 4473.64,5472.74 v1(4473.64,5453.74)
  Bottom Layer w10: v1(4473.64,5453.74) 4507.64,5419.74 4507.64,5201.74 4639.64,5069.74 5381.77,5069.74 5453.9,5141.87 U2.14
  other v1: 4427.64,5630.74
A_SIG: K10.2 R29.2 U7.2 | length 2550.5
  Inner1 w10: v1(4599.64,3955.74) 4599.64,3922.74 4734.64,3787.74 4760.64,3787.74 4915.64,3942.74 5088.64,3942.74 5222.64,4076.74 5222.64,4094.74 5244.64,4116.74 5801.64,4116.74 v1(6012.64,3905.74)
  Bottom Layer w10: U7.2 4305.64,3809.74 4309.61,3805.77 4378.25,3805.77 4425.46,3758.56 4569.72,3758.56 4592.93,3781.77 4663.84,3781.77 4673.84,3791.77 4736.85,3791.77 4736.85,3907.53 4730.64,3913.74 4730.64,3920.74 4718.64,3932.74 4706.64,3932.74 4683.64,3955.74 v1(4599.64,3955.74) ; v1(6012.64,3905.74) 6012.64,3902.74 v1@6013.64,3901.74
  other v1: 6000.64,3505.24
ADC-CS-0: U1.14 U6.10 | length 1479.4
  Inner1 w10: v1(4196.64,3589.74) 4710.64,3589.74 v1(5020.64,3899.74)
  Bottom Layer w10: U6.10 4082.64,3623.24 4116.14,3589.74 v1(4196.64,3589.74) ; v1(5020.64,3899.74) 5118.64,3997.74 5118.64,4150.74 5103.42,4165.96 U1.14
ADC-CS-1: U1.15 U7.10 | length 848.3
  Inner1 w10: v1(4706.64,3753.74) 4770.64,3753.74 v1(4920.64,3903.74)
  Bottom Layer w10: U7.10 4555.64,3704.84 4604.54,3753.74 v1(4706.64,3753.74) ; v1(4920.64,3903.74) 4953.64,3903.74 5101.64,4051.74 5101.64,4121.74 5090.89,4132.49 U1.15
AS_SIG: K11.2 R28.2 U7.3 | length 2793.5
  Inner1 w10: v1(4501.64,3955.74) 4673.64,3783.74 4673.64,3739.74 4683.64,3729.74 4782.64,3729.74 4978.64,3925.74 5136.64,3925.74 v1(5165.64,3954.74)
  Bottom Layer w10: U7.3 4355.64,3854.74 4404.64,3805.74 4404.64,3799.2 4429.87,3773.97 4565.31,3773.97 4587.13,3795.79 4635.69,3795.79 4652.64,3812.74 4652.64,3899.74 4625.64,3926.74 4583.64,3926.74 4554.64,3955.74 v1(4501.64,3955.74) ; v1(5165.64,3954.74) 5830.64,3954.74 R28.2
  other v1: 6283.39,4392.24
B_SIG: K12.2 R27.2 U7.4 | length 3512.9
  Inner1 w10: v1(4446.64,3802.74) 4379.64,3735.74 4075.64,3735.74 4043.64,3703.74 4043.64,3487.74 4416.64,3114.74 5267.64,3114.74 5326.64,3173.74 5399.64,3173.74 5422.64,3196.74 6449.14,3196.74 v1(6568.14,3315.74)
  Bottom Layer w10: U7.4 4405.64,3843.74 v1(4446.64,3802.74)
BOOT: SW2.2 U1.4 | length 2031.3
  Top Layer w10: v1(5912.64,3870.74) 5927.64,3855.74 v1(5927.64,3775.74)
  Inner1 w10: v1(5061.64,4499.74) 5516.64,4499.74 5942.64,4073.74 v1(5942.64,4012.74)
  Bottom Layer w10: v1(5912.64,3870.74) 5942.64,3900.74 v1(5942.64,4012.74) ; v1(5927.64,3775.74) 6034.58,3668.8 SW2.2
C_SIG: K1.2 R21.2 U6.1 | length 305.9
  Bottom Layer w10: v1(3564.64,3909.74) 3623.64,3968.74 3743.64,3968.74 3782.64,3929.74 U6.1
  other v1: 3271.41,4017.03
CAP0: U2.8 | length 643.8
  Top Layer w10: v1(5869.64,5593.74) 5870.64,5594.74 5870.64,5641.74
  Bottom Layer w10: U2.8 5654.64,5217.74 5869.64,5432.74 v1(5869.64,5593.74)
CAP1: U2.9 | length 834.9
  Top Layer w10: v1(6123.64,5588.74) 6160.64,5625.74 6160.64,5648.74
  Bottom Layer w10: U2.9 5664.89,5201.99 5907.64,5444.74 5979.64,5444.74 v1(6123.64,5588.74)
CAP2: U2.10 | length 1412.5
  Top Layer w10: v1(6603.64,5801.74) 6615.64,5813.74 6654.64,5813.74
  Bottom Layer w10: U2.10 5922.14,5186.24 6131.64,5395.74 6197.64,5395.74 6388.64,5586.74 6388.64,5624.74 6425.64,5661.74 6463.64,5661.74 v1(6603.64,5801.74)
CAP3: U2.11 | length 1502
  Top Layer w10: 6708.64,5417.74 6708.64,5418.74 v1(6772.64,5482.74)
  Inner1 w10: v1(6507.64,5490.74) 6764.64,5490.74 v1(6772.64,5482.74)
  Bottom Layer w10: U2.11 5996.01,5163.11 6323.64,5490.74 v1(6507.64,5490.74)
CAP4: U2.12 | length 700.7
  Top Layer w10: v1(6115.64,5134.74) 6150.64,5134.74 6158.64,5142.74
  Bottom Layer w10: U2.12 5485.4,5141.87 5492.53,5134.74 v1(6115.64,5134.74)
CAP5: U2.13 | length 557.2
  Top Layer w10: v1(5815.64,5109.74) 5956.64,5109.74 5977.64,5130.74
  Bottom Layer w10: U2.13 5469.65,5131.73 5490.64,5110.74 5814.64,5110.74 v1(5815.64,5109.74)
CS_SIG: K2.2 R14.2 U6.2 | length 251.2
  Bottom Layer w10: v1(3738.64,4094.74) 3832.64,4000.74 U6.2
  other v1: 3384.42,4282.07
D+: U1.24 U3.A6 U3.B6 | length 2035.7
  Bottom Layer w10: U3.A6 3375.41,3389.74 3411.64,3389.74 ; U3.B6 3406.11,3428.27 3417.64,3416.74 3417.64,3395.74 3411.64,3389.74 ; U1.24 4762.11,4090.17 4765.64,4086.63 4765.64,3635.37 4541.31,3411.03 3457.62,3411.03 3449.4,3402.81 3448.71,3402.81 3435.64,3389.74 3411.64,3389.74
D-: U1.23 U3.A7 U3.B7 | length 2093.2
  Bottom Layer w10: U3.A7 3373.73,3407.74 3340.64,3407.74 3332.64,3399.74 3332.64,3377.74 3341.17,3369.21 U3.B7 3439.11,3369.21 3460.71,3390.81 3460.71,3391.5 3464.25,3395.03 4547.93,3395.03 4781.64,3628.74 4781.64,4088.1 4783.71,4090.17 U1.23
D_SIG: K3.2 R15.2 U6.3 | length 544.3
  Top Layer w10: v1(3836.64,3795.74) 4086.64,3545.74 K3.2
  Bottom Layer w10: v1(3836.64,3795.74) 3882.64,3841.74 U6.3
  other v1: 3722.64,3903.74
DS_SIG: K4.2 R16.2 U6.4 | length 344.4
  Bottom Layer w10: U6.4 3932.64,4084.74 3999.8,4151.9 R16.2
  other v1: 4009.64,4197.74
E_SIG: K5.2 R17.2 U6.5 | length 1388.8
  Inner1 w10: v1(4111.64,4245.74) 4188.64,4322.74 4509.44,4322.74 4672.64,4159.54 4672.64,3940.74 v1(4704.64,3908.74)
  Bottom Layer w10: U6.5 3982.64,4085.74 4111.64,4214.74 v1(4111.64,4245.74) ; R17.2 4281.97,3463.07 v1(4304.64,3485.74)
EN: R10.2 SW3.2 U4.3 | length 384.9
  Top Layer w10: v1(3648.25,3205.43) 3653.64,3210.82 v1(3653.64,3311.74)
  Bottom Layer w10: U4.3 3584.25,3319.13 3659.12,3244.26 SW3.2 ; v1(3653.64,3311.74) 3708.98,3311.74 R10.2
F0: U7.5 U11.2 | length 2302.6
  Inner1 w10: v1(4301.64,3954.74) 4210.64,3954.74 4182.64,3982.74 4182.64,4021.74 4075.64,4128.74 4075.64,4274.74 4234.64,4433.74 4325.64,4433.74 4435.64,4543.74 4435.64,4860.74 4882.64,5307.74 v1(5085.64,5307.74)
  Bottom Layer w10: v1(4301.64,3954.74) 4421.14,3954.74 4455.64,3920.24 U7.5
F1: U7.6
F2: U7.7
F3: U7.8
F_SIG: K6.2 R18.2 U6.6 | length 1693.2
  Inner1 w10: v1(4106.64,4147.74) 4136.64,4177.74 4136.64,4221.74 4223.63,4308.72 4503.66,4308.72 4648.84,4163.55 4648.84,3904.55 4744.64,3808.74 4937.64,4001.74 v1(4972.64,4001.74)
  Bottom Layer w10: U6.6 4032.64,4073.74 v1(4106.64,4147.74)
  other v1: 4869.64,3705.74
FS_SIG: K7.2 R19.2 U6.7 | length 2120.4
  Inner1 w10: v1(4546.64,3501.74) 4598.64,3553.74 4716.64,3553.74 4832.64,3669.74 4873.64,3669.74 4893.64,3689.74 4893.64,3712.06 5084.21,3902.63 5147.37,3902.63 5198.5,3953.76 5198.5,4016.92 5255.64,4074.06 v1(5255.64,4086.74)
  Bottom Layer w10: U6.7 4067.64,3867.44 4067.64,3830.74 4031.64,3830.74 3908.64,3707.74 3908.64,3610.74 4094.33,3425.05 4469.95,3425.05 v1(4546.64,3501.74)
  other v1: 5554.64,4199.07
G_SIG: K8.2 R20.2 U6.8 | length 2218
  Inner1 w10: v1(4132.64,3853.74) 4014.64,3735.74 4014.64,3477.74 4414.64,3077.74 5616.64,3077.74 v1(5634.64,3095.74)
  other v1: 5861.13,3692.82
GND: C1.1 C2.2 C3.1 C4.1 C5.1 C6.1 C7.2 C8.2 C9.2 C10.1 C11.1 C12.1 CN1.1 CN1.3 CN1.4 CN3.1 CN4.1 CN5.1 LED2.4 LED3.4 LED4.4 LED5.4 P1.1 P3.1 R1.1 R2.1 R6.1 R8.1 R9.1 R12.2 R14.1 R15.1 R16.1 R17.1 R18.1 R19.1 R20.1 R21.1 R22.1 R27.1 R28.1 R29.1 R30.1 SW1.2 SW2.1 SW3.3 U1.1 U1.2 U1.42 U1.43 U1.46 U1.47 U1.48 U1.49 U1.50 U1.51 U1.52 U1.53 U1.54 U1.55 U1.56 U1.57 U1.58 U1.59 U1.60 U1.GND U2.6 U3.12 U3.13 U3.14 U3.15 U3.A1B12 U3.A12B1 U4.2 U5.2 U6.9 U6.14 U7.9 U7.14 U8.5 U9.10 U10.1 U10.4 U10.5 U11.3 | length 3812.1
  Bottom Layer w10: U3.14 U3.12 ; U3.15 U3.13@3338.62,3598.34 ; U3.13 3374.57,3562.41 U3.A12B1 3431.27,3524.73 R9.1 ; U3.A1B12 3374.57,3235.07 U3.12 ; LED2.4 3409.14,5546.24 v1(3448.64,5506.74) ; SW3.3 3600.07,3171.16 3570.64,3141.74 3392.64,3141.74 3338.63,3195.75 U3.12 ; v1(3878.64,5501.74) 3889.51,5512.61 LED3.4 ; C9.2 4180.2,3376.74 4287.3,3376.74 R12.2 4341.18,3343.74 4379.33,3305.58 4379.33,3226.05 ; U5.2 4367.64,3237.74 4379.33,3226.05 ; R6.1 4362.99,4007.75 C6.1 ; v1(4378.64,5501.74) 4389.51,5512.61 LED4.4 ; C7.2 4492.08,4727.3 4552.39,4666.99 U1.46 4554.78,4640.93 v1(5063.64,4640.93) ; C10.1 4422.48,3182.9 4379.33,3226.05 ; LED5.4 4903.64,5532.11 v1(4903.64,5496.74) ; v1(4918.18,3704.07) 5007.62,3614.63 CN1.4 ; U1.GND v1(5063.64,4640.93) ; v1(5063.64,4566.74) v1(5063.64,4640.93) ; C4.1 5064.27,4640.3 v1(5063.64,4640.93) ; v1(5483.07,5402.55) 5544.39,5402.55 C1.1 5611.98,5334.96 R1.1 5555.16,5249.24 U2.6 ; U10.4@6459.11,5076.54 U10.5@6459.11,5126.94 ; U10.1@6518.17,5076.54 6576.44,5076.54 ; C12.1 6555.89,5219.49 6637.64,5137.74 ; C11.1 6590.2,5062.78 6576.44,5076.54 ; U8.5 6682.83,5137.74 6637.64,5137.74 ; v1(6768.64,5024.2) 6770.2,5022.64 C5.1 ; 6576.44,5076.54 6637.64,5137.74
  other v1: 5440.64,3153.92 3368.64,3156.74 5912.92,3159.03 6505.15,3315.74 5020.64,3318.74 3623.64,3351.74 3543.64,3356.74 4208.64,3366.74 4207.23,3463.07 5933.49,3505.24 4782.11,3522.11 3161.46,3555.74 4132.64,3657.06 4603.64,3656.74 5922.38,3677.07 4348.64,3696.74 3878.64,3706.74 3646.64,3909.74 4358.64,4073.74 3283.3,4095.58 3938.64,4199.07 5629.7,4199.07 3318.4,4282.07 3181,4364.06 7001,4364.06 6212.89,4392.24 4512.04,4500.6 4512.04,4534.07 5061.25,4601 5650,4603.24 6447.3,5072.05 6294.97,5150.54 5301.08,5262.74 3137.87,5306.74 6447.64,5383.74 5123.64,5906.74 6128.64,5906.74 5623.64,5911.74
GS_SIG: K9.2 R22.2 U7.1 | length 1831.1
  Inner1 w10: v1(4715.64,3956.74) 4794.64,4035.74 5135.64,4035.74 5239.64,4139.74 5624.64,4139.74 5629.64,4144.74 v1(5675.64,4144.74)
  Bottom Layer w10: U7.1 4255.64,3823.74 4254.64,3822.74 4285.63,3791.76 4372.45,3791.76 4428.46,3735.74 4566.72,3735.74 4598.74,3767.76 4669.64,3767.76 4679.64,3777.76 4742.66,3777.76 4751.64,3786.74 4751.64,3920.74 v1(4715.64,3956.74)
  other v1: 5725.64,4595.74
MISO: U1.33 U6.12 U7.12 | length 1277.3
  Bottom Layer w10: U6.12 3982.64,3751.74 4038.64,3807.74 4121.64,3807.74 4174.64,3860.74 ; U7.12 4455.64,3688.74 4366.64,3777.74 4257.64,3777.74 4174.64,3860.74 ; U1.33 4346.32,4199.42 4174.64,4027.74 4174.64,3860.74
MOSI: U1.31 U6.11 U7.11 | length 1493.9
  Top Layer w10: v1(4198.64,3784.74) v1(4198.64,3876.74)
  Bottom Layer w10: U6.11 U6.11@4028.64,3663.04 ; v1(4198.64,3784.74) 4197.64,3783.74 4063.64,3783.74 4028.64,3748.74 U6.11@4028.64,3663.04 ; v1(4198.64,3876.74) 4198.64,4000.74 4318.64,4120.74 4500.29,4120.74 U1.31 ; U7.11 4505.64,3617.24 4432.14,3543.74 4091.64,3543.74 4028.64,3606.74 U6.11@4028.64,3663.04
NEO: LED2.1 U1.28 | length 2629.1
  Top Layer w10: v1(4479.64,4483.74) 4499.64,4463.74 v1(4554.64,4463.74)
  Bottom Layer w10: LED2.1 3247.78,4739.6 3503.64,4483.74 v1(4479.64,4483.74) ; v1(4554.64,4463.74) 4619.32,4399.06 U1.28
PWR_SENS: R31.2 U1.9 | length 1808.5
  Top Layer w10: v1(6203.64,4631.74) 6203.64,4469.74 v1(6205.64,4467.74)
  Bottom Layer w10: U1.9 5184.18,4333.28 5250.64,4399.74 5285.64,4399.74 5304.64,4418.74 6156.64,4418.74 v1(6205.64,4467.74) ; v1(6203.64,4631.74) 6359.6,4787.7 R31.2
RST: C7.1 R7.2 SW1.1 U1.45 | length 2188.6
  Top Layer w10: v1(5354.64,4010.74) 5356.64,4008.74 v1(5356.64,3768.74)
  Inner1 w10: v1(4585.64,4589.74) 4619.64,4555.74 4805.64,4555.74 4900.64,4460.74 4900.64,4352.74 4967.64,4285.74 5117.64,4285.74 v1(5157.64,4245.74)
  Bottom Layer w10: C7.1 4434.12,4649.7 R7.2 4436.01,4601 U1.45 4574.38,4601 v1(4585.64,4589.74) ; v1(5157.64,4245.74) 5354.64,4048.74 v1(5354.64,4010.74) ; SW1.1 5332.7,3744.8 v1(5356.64,3768.74)
RX0: P2.1 U1.40 | length 1484.1
  Bottom Layer w10: P2.1 3502.14,4064.06 3825.84,4387.76 4302.86,4387.76 4346.84,4431.74 4510.11,4431.74 U1.40
RX1: P4.2 U1.22 | length 2464.4
  Bottom Layer w10: U1.22 4820.11,3913.27 4922.64,3810.74 6829.64,3810.74 6984.54,3965.64 P4.2
RX2: R23.1 U1.34 U8.4 | length 3529.1
  Top Layer w10: v1(4588.64,4138.74) 4944.64,4138.74 v1(5008.64,4202.74)
  Inner1 w10: v1(5008.64,4202.74) 5150.64,4202.74 5274.64,4326.74 5198.64,4402.74 5046.64,4402.74 5024.64,4424.74 5024.64,4515.74 5034.64,4525.74 6562.64,4525.74 6901.64,4864.74 v1@6901.64,4934.74
  Bottom Layer w10: U1.34 4532.79,4232.89 4545.64,4220.04 4545.64,4181.74 v1(4588.64,4138.74) ; U8.4 6855.64,4972.08 R23.1 6863.64,4971.74 v1(6900.64,4934.74)
SCK: U1.32 U6.13 U7.13 | length 1916.2
  Top Layer w10: v1(4223.64,3516.74) 4223.64,3981.74 v1(4224.64,3982.74)
  Inner1 w10: v1(4224.64,3982.74) 4387.64,4145.74 v1(4414.64,4145.74)
  Bottom Layer w10: U6.13 3932.64,3623.24 4039.14,3516.74 v1(4223.64,3516.74) 4434.64,3516.74 4528.64,3610.74 4528.64,3703.74 4512.64,3719.74 4498.64,3719.74 4478.64,3699.74 4478.64,3623.74 4456.64,3601.74 4425.64,3601.74 4405.64,3621.74 U7.13 ; v1(4414.64,4145.74) 4434.86,4165.96 U1.32
SCL: R4.2 U1.8 U2.2 U9.2 | length 3275.5
  Top Layer w10: v1(5451.64,5203.74) 5467.64,5203.74 5617.64,5053.74 5617.64,4572.74 5657.64,4532.74 v1(5657.64,4444.74)
  Bottom Layer w10: U1.8 5167.1,4366.74 R4.2 ; v1(5451.64,5203.74) 5451.64,5248.87 5453.9,5251.13 U2.2 ; v1@5662.64,4445.74 5656.64,4445.74 5640.37,4462.01 R4.2 ; U9.2@6415.32,5189.24 6415.32,5140.42 6412.66,5137.76 6412.66,4758.93 6130.45,4476.72 5277.09,4476.72 R4.2
SDA: R5.2 U1.7 U2.3 U9.3 | length 2792.7
  Top Layer w10: v1(5489.64,5214.74) 5647.64,5056.74 5647.64,4647.74 v1(5656.64,4638.74)
  Bottom Layer w10: U1.7 5137.87,4400.21 R5.2 ; R5.2@5197.37,4461.71 5226.4,4490.74 5678.99,4490.74 ; U2.3 5469.65,5234.73 v1(5489.64,5214.74) ; v1(5656.64,4638.74) 5673.65,4638.74 5679.64,4632.75 5679.64,4491.39 5678.99,4490.74 ; U9.3@6396.64,5190.24 6396.64,4764.74 6122.64,4490.74 5678.99,4490.74
TX0: P2.2 U1.39 | length 1512.3
  Bottom Layer w10: P2.2 3423.54,3965.64 3831.64,4373.74 4308.64,4373.74 4336.64,4401.74 4510.51,4401.74 U1.39
TX1: P4.1 U1.21 | length 2468.1
  Bottom Layer w10: U1.21 4853.57,3899.63 4928.45,3824.76 6746.66,3824.76 6985.96,4064.06 P4.1
TX2: R26.2 U1.35 | length 2111.5
  Top Layer w10: v1(4590.64,4177.74) 4590.64,4258.74 4619.64,4287.74 4619.64,4613.74 v1(4693.64,4687.74) ; v1(5088.64,5032.74) 5088.64,5204.74 v1(5220.64,5336.74)
  Bottom Layer w10: U1.35 4543.03,4266.35 4561.64,4247.74 4561.64,4206.74 v1(4590.64,4177.74) ; v1(4693.64,4687.74) 4743.64,4687.74 v1(5088.64,5032.74) ; v1(5220.64,5336.74) 5383.64,5499.74 5383.64,5619.51 5490.16,5726.02 R26.2
VUSB: D1.2 LED1.1 Q1.1 R11.2 U3.A4B9 U3.A9B4 U5.4 U10.6 | length 5786.3
  Top Layer w10: v1(3926.64,4309.74) 3931.64,4314.74 v1(3931.64,4517.74) ; v1(4500.64,4988.74) 4575.64,4913.74 v1(5027.64,4913.74) ; v1(6368.64,5109.74) 6373.64,5104.74 v1(6435.64,5104.74)
  Inner1 w20: v1(3403.64,3303.74) 3628.64,3078.74 4037.64,3078.74 v1(4074.64,3115.74)
  Bottom Layer w10: U3.A4B9 3371.03,3307.79 3336.59,3307.79 3293.64,3350.74 3293.64,3445.84 3341.03,3493.23 U3.A9B4 3400.16,3493.23 3417.64,3510.71 3437.08,3510.71 3439.97,3513.74 3488.64,3513.74 3498.64,3523.74 3498.64,3556.74 3444.64,3610.74 3444.64,3872.74 3881.64,4309.74 v1(3926.64,4309.74) ; R11.2 3969.28,3229.08 D1.2 4005.19,3195.72 LED1.1 4090.44,3159.01 Q1.1 4249.22,3199.34 U5.4 ; v1(3931.64,4517.74) 3974.64,4517.74 4445.64,4988.74 v1(4500.64,4988.74) ; v1(5027.64,4913.74) 5125.64,5011.74 5781.64,5011.74 5879.64,5109.74 v1(6368.64,5109.74) ; v1(6435.64,5104.74) 6435.64,5140.74 6444.64,5149.74 6469.64,5149.74 6469.89,5149.99 6478.8,5141.08 U10.6@6478.8,5126.94
"": CN2.1 CN2.2 CN2.5 CN3.2 CN3.5 CN4.2 CN4.3 CN4.5 CN5.2 CN5.3 CN5.5 LED5.3 P1.3 P1.4 P2.3 P2.4 P3.3 P3.4 P4.3 P4.4 pad.73 Q1.2 SW1.3 SW1.4 SW2.3 SW2.4 SW3.1 SW3.4 SW3.5 SW3.6 SW3.7 U1.5 U1.6 U1.10 U1.11 U1.12 U1.13 U1.16 U1.17 U1.18 U1.19 U1.20 U1.25 U1.26 U1.27 U1.30 U1.36 U1.37 U1.38 U1.41 U1.44 U1.61 U1.62 U1.63 U1.64 U1.65 U1.66 U1.67 U1.68 U1.69 U1.70 U1.71 U1.72 U3.A8 U3.B8 U4.4 U8.3 U9.5 U9.8 U9.9

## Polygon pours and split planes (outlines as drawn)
GND on Inner2 (split plane): 7058.54,3146.74 cw(c7013.59,3101.79) 6968.64,3056.84 3168.64,3056.84 cw(c3123.69,3101.79) 3078.74,3146.74 3078.74,5946.74 cw(c3123.69,5991.69) 3168.64,6036.64 6968.64,6036.64 cw(c7013.59,5991.69) 7058.54,5946.74 7058.54,3146.74

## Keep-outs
Bottom Layer:
  region net "": 4480.84,4671.85 5089.79,4671.85 5089.79,5046.74 4480.84,5046.74
Board Outline Layer:
  lines w10 net "": 3068.64,3146.74 ccw(c3168.64,3146.74) 3168.64,3046.74 6968.64,3046.74 ccw(c6968.64,3146.74) 7068.64,3146.74 7068.64,5946.74 ccw(c6968.64,5946.74) 6968.64,6046.74 3168.64,6046.74 ccw(c3168.64,5946.74) 3068.64,5946.74 3068.64,3146.74

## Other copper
Top Layer:
  region net CAP0: 5985.46,5973.52 5961.13,5882.69 cw(c5808.69,5796.74) 5722.74,5644.3 5631.91,5619.96 5656.25,5710.79 cw(c5808.69,5796.74) 5894.64,5949.18
  region net CAP5: 5991.19,5121.74 5641.19,5296.74 5991.19,5471.74 5916.19,5296.74
  region net CAP4: 6141.19,5121.74 6316.19,5471.74 6491.19,5121.74 6316.19,5196.74
  region net CAP3: 6641.19,5471.74 6716.19,5296.74 6641.19,5121.74 6991.19,5296.74
  region net "": 6611.19,5531.74 7036.19,5531.74 ccw(c7036.19,5546.74) 7036.19,5561.74 6611.19,5561.74 ccw(c6611.19,5546.74)
  region net "": 6551.19,6016.74 6551.19,5076.74 ccw(c6566.19,5076.74) 6581.19,5076.74 6581.19,6016.74 ccw(c6566.19,6016.74)
  region net "": 6521.19,5561.74 6111.19,5561.74 ccw(c6111.19,5546.74) 6111.19,5531.74 6521.19,5531.74 ccw(c6521.19,5546.74)
  region net "": 5596.19,5561.74 6021.19,5561.74 cw(c6021.19,5546.74) 6021.19,5531.74 5596.19,5531.74 cw(c5596.19,5546.74)
  region net "": 6051.19,6016.74 6051.19,5076.74 ccw(c6066.19,5076.74) 6081.19,5076.74 6081.19,6016.74 ccw(c6066.19,6016.74)
  region net CAP1: 6137.18,5617.29 6317.77,5655.41 6494.59,5617.92 6493.64,5836.74 6411.64,5986.74 6317.84,6027.71 6223.94,5988.62 6136.66,5829.85
  region net CAP2: 6791.19,5971.48 6791.19,5971.74 6641.19,5971.74 6641.19,5621.74 6818.64,5621.74 6992.64,5796.74 6804.9,5971.48

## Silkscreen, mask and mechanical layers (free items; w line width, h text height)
Top Silkscreen Layer:
  region net "": 3676.64,3055.74 3676.64,4055.74 4176.64,4055.74 4176.64,3055.74
  region net "": 4247.64,3055.74 4247.64,4055.74 4747.64,4055.74 4747.64,3055.74
  region net "": 4819.64,3055.74 4819.64,4055.74 5319.64,4055.74 5319.64,3055.74
  region net "": 5390.64,3055.74 5390.64,4055.74 5890.64,4055.74 5890.64,3055.74
  region net "": 5961.64,3055.74 5961.64,4055.74 6461.64,4055.74 6461.64,3055.74
  region net "": 3140.74,3055.74 3104.64,3075.74 3104.64,4055.74 3604.64,4055.74 3604.64,3055.74
  region net "": 6993.64,3055.74 7033.64,3095.74 7033.64,4055.74 6533.64,4055.74 6533.64,3055.74
  text "KS-12 \"PUPNIK\" RESISTIVE CONTROLLER" at 3178.64,5936.74 h90
  text "BLE MIDI" at 4478.64,4897.74 h130
Top Solder Mask Layer:
  region net "": 6551.19,6016.74 6551.19,5076.74 ccw(c6566.19,5076.74) 6581.19,5076.74 6581.19,6016.74 ccw(c6566.19,6016.74)
  region net "": 6051.19,6016.74 6051.19,5076.74 ccw(c6066.19,5076.74) 6081.19,5076.74 6081.19,6016.74 ccw(c6066.19,6016.74)
  region net "": 6611.19,5531.74 7036.19,5531.74 ccw(c7036.19,5546.74) 7036.19,5561.74 6611.19,5561.74 ccw(c6611.19,5546.74)
  region net "": 5596.19,5561.74 6021.19,5561.74 cw(c6021.19,5546.74) 6021.19,5531.74 5596.19,5531.74 cw(c5596.19,5546.74)
  region net "": 6521.19,5561.74 6111.19,5561.74 ccw(c6111.19,5546.74) 6111.19,5531.74 6521.19,5531.74 ccw(c6521.19,5546.74)
  region net "": 6141.19,5121.74 6316.19,5471.74 6491.19,5121.74 6316.19,5196.74
  region net "": 5991.19,5121.74 5641.19,5296.74 5991.19,5471.74 5916.19,5296.74
  region net "": 6641.19,5471.74 6716.19,5296.74 6641.19,5121.74 6991.19,5296.74
  region net "": 5985.46,5973.52 5961.13,5882.69 cw(c5808.69,5796.74) 5722.74,5644.3 5631.91,5619.96 5656.25,5710.79 cw(c5808.69,5796.74) 5894.64,5949.18
  region net "": 6141.19,5736.93 6218.69,5825.5 6218.69,5975.5 6141.19,5836.93
  region net "": 6228.69,5988.53 6306.19,6021.74 6306.19,5865.83 6228.69,5832.62
  region net "": 6413.69,5975.5 6491.19,5836.93 6491.19,5736.93 6413.69,5825.5
  region net "": 6641.19,5971.74 6691.19,5971.74 6691.19,5621.74 6641.19,5621.74
  region net "": 6716.19,5971.74 6766.19,5971.74 6766.19,5621.74 6716.19,5621.74
  region net "": 6791.19,5971.74 6991.19,5796.74 6791.19,5621.74 6866.19,5796.74
  region net "": 6141.19,5619.77 cw(c6141.19,5621.74) 6139.22,5621.74 6139.22,5721.74 cw(c6141.19,5721.74) 6139.71,5723.04 6227.21,5823.04 cw(c6228.69,5821.74) 6227.91,5823.55 6315.41,5861.05 cw(c6316.19,5859.24) 6316.19,5861.21 cw(c6316.19,5859.24) 6316.96,5861.05 6404.46,5823.55 cw(c6403.69,5821.74) 6405.17,5823.04 6492.67,5723.04 cw(c6491.19,5721.74) 6493.15,5721.74 6493.15,5621.74 cw(c6491.19,5621.74) 6491.19,5619.77 cw(c6491.19,5621.74) 6490.77,5619.82 6316.19,5657.23 6141.6,5619.82 cw(c6141.19,5621.74)
  region net "": 6326.19,5865.83 6326.2,5865.85 6326.19,6021.74 6403.69,5988.53 6403.69,5832.62
  text "P" at 3608.64,3246.74 h100
  text "R" at 5317.64,3246.74 h100
  text "B" at 5892.64,3246.74 h100
Bottom Solder Mask Layer:
  region net "": 3118.64,5646.74 5043.64,5646.74 5043.64,5946.74 3118.64,5946.74
Mech6:
  circle w3.94 net "": c3247.21,4546.74 r62.99
  circle w3.94 net "": c6890.07,4546.74 r62.99
  lines w3.94 net "": 3068.64,5046.74 7068.64,5046.74 ; 3104.36,3070.14 3104.36,5046.74 ; 3168.64,3046.74 6968.64,3046.74 ; 3390.07,5046.74 3390.07,4046.74 3890.07,4046.74 3890.07,5046.74 ; 3604.36,3046.74 3604.36,4046.74 ; 3675.78,3046.74 3675.78,4046.74 ; 3961.5,5046.74 3961.5,4046.74 4461.5,4046.74 4461.5,5046.74 ; 4175.78,3046.74 4175.78,4046.74 ; 4247.21,3046.74 4247.21,4046.74 ; 4747.21,3046.74 4747.21,4046.74 4747.21,5046.74 ; 4818.64,3046.74 4818.64,4046.74 4818.64,5046.74 ; 5104.36,5046.74 5104.36,4046.74 5604.36,4046.74 5604.36,5046.74 ; 5318.64,3046.74 5318.64,4046.74 ; 5390.07,3046.74 5390.07,4046.74 ; 5675.78,5046.74 5675.78,4046.74 6175.78,4046.74 6175.78,5046.74 ; 5890.07,3046.74 5890.07,4046.74 ; 5961.5,3046.74 5961.5,4046.74 ; 6247.21,5046.74 6247.21,4046.74 6747.21,4046.74 6747.21,5046.74 ; 6461.5,3046.74 6461.5,4046.74 ; 6532.93,3046.74 6532.93,4046.74 ; 7032.93,3070.14 7032.93,5046.74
